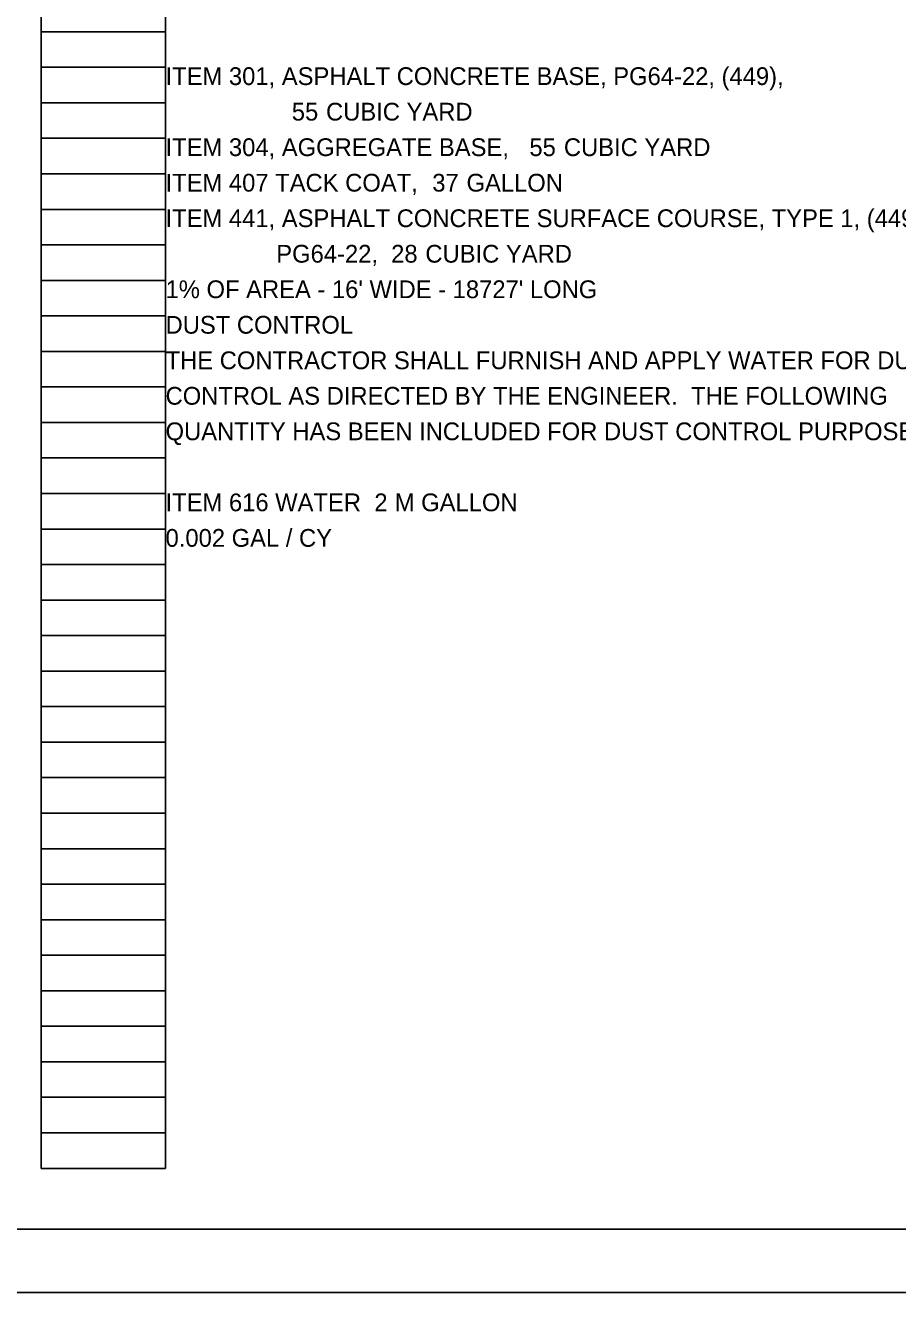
# Model space of a CAD drawing. Extents: x -8.6 to 34, y 0 to 22.
# Drawn here: x 23.56 to 30.43, y 0 to 9.99 of the extents above; entities that cross this region are included whole.
import ezdxf

# ---------------------------------------------------------------- set-up
doc = ezdxf.new("R2010")
doc.units = 0
for name, color, linetype in [('SC_Scratch1', 7, 'Continuous'), ('SC_Scratch2', 7, 'Continuous'), ('SH_Border', 7, 'Continuous'), ('SH_Cut_Line', 7, 'Continuous'), ('SH_Text', 7, 'Continuous')]:
    doc.layers.add(name, color=color, linetype=linetype)

msp = doc.modelspace()

# ---------------------------------------------------------------- linework, layer by layer
at = {"layer": 'SC_Scratch1'}
for p, q in [((23.68, 0.98), (23.68, 21.14)), ((24.66, 0.98), (24.66, 21.14)), ((23.68, 9.94), (24.66, 9.94)), ((23.68, 9.66), (24.66, 9.66)), ((23.68, 9.38), (24.66, 9.38)), ((23.68, 9.1), (24.66, 9.1)), ((23.68, 8.82), (24.66, 8.82)), ((23.68, 8.54), (24.66, 8.54)), ((23.68, 8.26), (24.66, 8.26)), ((23.68, 7.98), (24.66, 7.98)), ((23.68, 7.7), (24.66, 7.7)), ((23.68, 7.42), (24.66, 7.42)), ((23.68, 7.14), (24.66, 7.14)), ((23.68, 6.86), (24.66, 6.86)), ((23.68, 6.58), (24.66, 6.58)), ((23.68, 6.3), (24.66, 6.3)), ((23.68, 6.02), (24.66, 6.02)), ((23.68, 5.74), (24.66, 5.74)), ((23.68, 5.46), (24.66, 5.46)), ((23.68, 5.18), (24.66, 5.18)), ((23.68, 4.9), (24.66, 4.9)), ((23.68, 4.62), (24.66, 4.62)), ((23.68, 4.34), (24.66, 4.34)), ((23.68, 4.06), (24.66, 4.06)), ((23.68, 3.78), (24.66, 3.78)), ((23.68, 3.5), (24.66, 3.5)), ((23.68, 3.22), (24.66, 3.22)), ((23.68, 2.94), (24.66, 2.94)), ((23.68, 2.66), (24.66, 2.66)), ((23.68, 2.38), (24.66, 2.38)), ((23.68, 2.1), (24.66, 2.1)), ((23.68, 1.82), (24.66, 1.82)), ((23.68, 1.54), (24.66, 1.54)), ((23.68, 1.26), (24.66, 1.26)), ((23.68, 0.98), (24.66, 0.98))]:
    msp.add_line(p, q, dxfattribs=at)
at = {"layer": 'SH_Border'}
msp.add_lwpolyline([(1.5, 21.5), (33.5, 21.5), (33.5, 0.5), (1.5, 0.5)], close=True, dxfattribs=at)
at = {"layer": 'SH_Cut_Line'}
msp.add_lwpolyline([(0, 0), (34, 0), (34, 22), (0, 22)], close=True, dxfattribs=at)

# ---------------------------------------------------------------- texts
at = {"layer": 'SC_Scratch2'}
for s, p in [("1% OF AREA - 16' WIDE - 18727' LONG", (24.66, 7.84)), ('0.002 GAL / CY', (24.66, 5.88))]:
    msp.add_text(s, height=0.14, dxfattribs=at).set_placement(p)
at = {"layer": 'SH_Text'}
for s, p in [('ITEM 301, ASPHALT CONCRETE BASE, PG64-22, (449),', (24.66, 9.52)), ('55', (25.6545, 9.24)), (' CUBIC YARD', (25.872, 9.24)), ('ITEM 304, AGGREGATE BASE, ', (24.66, 8.96)), ('55 ', (27.5262, 8.96)), ('CUBIC YARD', (27.7979, 8.96)), ('ITEM 407 TACK COAT, ', (24.66, 8.68)), ('37', (26.7613, 8.68)), (' GALLON', (26.9787, 8.68)), ('ITEM 441, ASPHALT CONCRETE SURFACE COURSE, TYPE 1, (449), ', (24.66, 8.4)), ('      PG64-22, ', (25.22, 8.12)), ('28', (26.4372, 8.12)), (' CUBIC YARD', (26.6547, 8.12)), ('DUST CONTROL', (24.66, 7.56)), ('THE CONTRACTOR SHALL FURNISH AND APPLY WATER FOR DUST ', (24.66, 7.28)), ('CONTROL AS DIRECTED BY THE ENGINEER.  THE FOLLOWING ', (24.66, 7)), ('QUANTITY HAS BEEN INCLUDED FOR DUST CONTROL PURPOSES:', (24.66, 6.72)), ('ITEM 616 WATER ', (24.66, 6.16)), ('2', (26.3048, 6.16)), (' M GALLON', (26.4135, 6.16))]:
    msp.add_text(s, height=0.14, dxfattribs=at).set_placement(p)

doc.saveas('drawing.dxf')
